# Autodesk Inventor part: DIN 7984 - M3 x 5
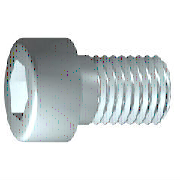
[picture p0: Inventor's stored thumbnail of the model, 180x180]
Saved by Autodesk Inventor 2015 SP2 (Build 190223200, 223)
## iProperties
Created: 2012-02
Part Number: DIN 7984 - M3 x 5
Material: Steel, Mild
Description: Cylinder Head Cap Screw
Document SubType Name: Modeling
Standard: DIN 7984
Designer: rYan
Standard Revision: 1985
Standards Organization: DIN
Language: en-US
Size Designation: M3 x 5
Categories: <MemberInstance><Categories><Category DisplayName="Fasteners" InternalName="e4da775c-781d-43d5-af7c-5136215cf5a6" Mnemonic="FSTN"><Category DisplayName="Bolts"
Density: 7.85 g/cm^3
Appearance: Halbpoliert
IsCustomPart: 0
Author: rYan
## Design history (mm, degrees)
sketch "Sketch1"
  geometry: L1 (0.167, 0)-(5, 0); L2 (5, 0)-(5, 1.5); L3 (5, 1.5)-(1.5, 1.5); L4 (1.5, 1.5)-(1.193, 1.5); L5 (1.193, 1.5)-(0, 1.5); L6 (0, 1.5)-(0, 2.75); L7 (0, 2.75)-(-2, 2.75); L8 (-2, 2.75)-(-2, 1.155); L9 (-2, 1.155)-(-0.5, 1.155); L10 (-0.5, 1.155)-(0.167, 0); L11 (-3.4, 0)-(6.4, 0) reference; L12 (0, -0.55)-(0, 3.3) reference; L13 (1.5, 1.5)-(0, 1.5)
  constraints: 22 end point, 6 parallel, 2 collinear, 2 perpendicular, 1 horizontal, 1 point on line
  dimensions: "d1" = 3.5 distance from line of L3.end L2 (= GEL); "d2" = 0.30683 distance of L4.end L3.end (computed from GAL); "d3" = 2 distance between parallel lines of L8 L6 (= KOH); "d4" = 1.5 distance of L8.end L9.end (= INTI); "d5" = 60 deg angle of L10 L1; "d6" = 3 diameter of L3 L1 (= GD); "d7" = 3 diameter of L5 L1 (= BDM); "d8" = 2.3094 diameter of L9 L1 (= 1.1547 x SW); "d9" = 5.5 diameter of L7 L1 (= KOD); "d26" = 5 distance between parallel lines of L12 L2 (= NLG)
revolve "Body" sketch "Sketch1" stored, may be unused: angle "d10" = 90 deg
sketch "Sketch2"
  geometry: L1 (0, -3.85)-(0, 3.85) reference; L2 (-3.85, 0)-(3.85, 0) reference; L3 (1.155, 0)-(0.577, -1); L4 (0.577, -1)-(-0.577, -1); L5 (-0.577, -1)-(-1.155, 0); L6 (-1.155, 0)-(-0.577, 1); L7 (-0.577, 1)-(0.577, 1); L8 (0.577, 1)-(1.155, 0); 2 further points
  constraints: 12 end point, 1 coincident, 1 horizontal alignment, 1 point on line, 12 other
extrude "Slot" join sketch "Sketch2" stored distance "d11" = 10; taper "d12" = 0 deg
fillet "Fillet1" dims "d17" = 0.3 (= RR)
feature "Thread" dims "d13" = 3.5 (= GEL), "d14" = 0
chamfer "Chamfer1" distance "d15" = 0.30673 (= -0.5 x SPD + 0.5 x GD); stored, may be unused: second distance "d16" = 0.30673 (= GUL), angle "d27" = 45 deg
workplane "Work Plane1"
fillet "Fillet2" dims "d30" = 0.1 (= R)
body "Solid1"
other parameters: "GD" = 3 (= NND) [user parameter; used in 2 equation terms], "NLG" = 5 [user parameter; used in 1 equation term], "GEL" = 3.5 [user parameter; used in 2 equation terms], "KOD" = 5.5 [user parameter; used in 1 equation term], "KOH" = 2 [user parameter; used in 1 equation term], "INTI" = 1.5 [user parameter; used in 1 equation term], "GAL" = 0.30673 (= 0.61345 x PTC) [user parameter; used in 1 equation term], "GUL" = 0.30673 (= 0.61345 x PTC) [user parameter; used in 1 equation term], "BDM" = 3 (= NND) [user parameter; used in 1 equation term], "SW" = 2 [user parameter; used in 2 equation terms], "RR" = 0.3 [user parameter; used in 1 equation term], "SPD" = 2.38655 (= NND - 1.2269 x PTC) [user parameter; used in 1 equation term], "d19" = 0, "d28" = 0, "d29" = 0, "R" = 0.1 [user parameter; used in 1 equation term], "TOA" = 30 deg [user parameter], "GD1" = 2.38655 (= THREADDIA - 1.2269 x PTC) [user parameter], "THREADDIA" = 3 [user parameter; used in 1 equation term], "FAWI" = 45 deg [user parameter], "ANG" = 120 deg [user parameter], "PTC" = 0.5 [user parameter; used in 5 equation terms], "NND" = 3 [user parameter; used in 3 equation terms], "E0" = 2.31 (= 1.155 x SW) [user parameter]
